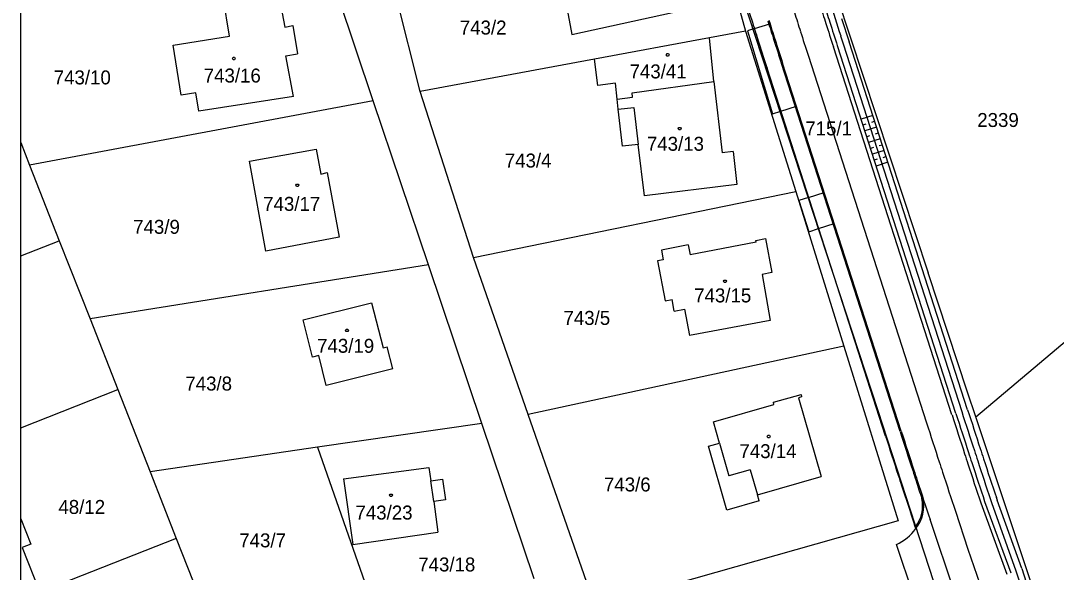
# Model space of a CAD drawing. Extents: x -639590 to -639298, y -1193269 to -1192863.
# Drawn here: x -639590.4 to -639464.3, y -1193117.1 to -1193049.8 of the extents above; entities that cross this region are included whole.
import ezdxf

# ---------------------------------------------------------------- set-up
doc = ezdxf.new("R2010")
doc.units = 0
for name, color, linetype in [('Vrstva 1', 7, 'Continuous'), ('Vrstva 19', 7, 'Continuous'), ('Vrstva 2', 7, 'Continuous'), ('Vrstva 20', 7, 'Continuous'), ('Vrstva 21', 7, 'Continuous'), ('Vrstva 4', 7, 'Continuous'), ('Vrstva 5', 7, 'Continuous'), ('Vrstva 61', 7, 'Continuous')]:
    doc.layers.add(name, color=color, linetype=linetype)

msp = doc.modelspace()

# ---------------------------------------------------------------- linework, layer by layer
at = {"layer": 'Vrstva 1'}
for p, q in [((-639507.5, -1193031.78), (-639502.09, -1193051.09)), ((-639506.87, -1193033.57), (-639486.01, -1193097.33)), ((-639547.47, -1193059.58), (-639554.02, -1193040.01)), ((-639559.45, -1193044.19), (-639558.24, -1193050.62)), ((-639541.72, -1193058.45), (-639545.4, -1193043.83)), ((-639492.18, -1193043.2), (-639479.86, -1193080.55)), ((-639564.97, -1193051.71), (-639566.02, -1193045.25)), ((-639524.07, -1193047.11), (-639523.28, -1193051.49)), ((-639523.28, -1193051.49), (-639511.02, -1193048.83)), ((-639558.24, -1193050.62), (-639557.26, -1193050.41)), ((-639557.26, -1193050.41), (-639556.66, -1193053.85)), ((-639571.83, -1193052.82), (-639564.97, -1193051.71)), ((-639506.48, -1193051.9), (-639520.51, -1193054.51)), ((-639502.09, -1193051.09), (-639506.48, -1193051.9)), ((-639505.97, -1193057.23), (-639506.48, -1193051.9)), ((-639502.09, -1193051.09), (-639495.98, -1193070.66)), ((-639570.85, -1193058.91), (-639571.83, -1193052.82)), ((-639474.06, -1193098.11), (-639420.3, -1193052.71)), ((-639558.11, -1193054.1), (-639556.66, -1193053.85)), ((-639557.17, -1193059.07), (-639558.11, -1193054.1)), ((-639520.51, -1193054.51), (-639541.72, -1193058.45)), ((-639520.08, -1193057.71), (-639520.51, -1193054.51)), ((-639517.95, -1193057.42), (-639520.08, -1193057.71)), ((-639517.76, -1193059.39), (-639517.95, -1193057.42)), ((-639515.93, -1193058.62), (-639505.97, -1193057.23)), ((-639505.97, -1193057.23), (-639504.97, -1193065.92)), ((-639569.05, -1193058.62), (-639570.85, -1193058.91)), ((-639568.69, -1193060.84), (-639569.05, -1193058.62)), ((-639557.17, -1193059.07), (-639568.69, -1193060.84)), ((-639535.24, -1193078.67), (-639541.72, -1193058.45)), ((-639517.76, -1193059.39), (-639515.86, -1193059.16)), ((-639517.61, -1193060.62), (-639517.76, -1193059.39)), ((-639515.86, -1193059.16), (-639515.93, -1193058.62)), ((-639547.47, -1193059.58), (-639589.3, -1193067.44)), ((-639540.73, -1193079.59), (-639547.47, -1193059.58)), ((-639517.08, -1193065.13), (-639517.61, -1193060.62)), ((-639590.39, -1193064.66), (-639589.3, -1193067.44)), ((-639562.54, -1193066.96), (-639554.39, -1193065.47)), ((-639554.39, -1193065.47), (-639553.85, -1193068.54)), ((-639515.18, -1193064.91), (-639517.08, -1193065.13)), ((-639514.42, -1193071.19), (-639515.18, -1193064.91)), ((-639503.63, -1193065.77), (-639504.97, -1193065.92)), ((-639503.63, -1193065.77), (-639503.17, -1193069.78)), ((-639560.52, -1193077.92), (-639562.54, -1193066.96)), ((-639589.3, -1193067.44), (-639585.69, -1193076.64)), ((-639553.85, -1193068.54), (-639553.06, -1193068.33)), ((-639553.06, -1193068.33), (-639551.62, -1193076.2)), ((-639535.24, -1193078.67), (-639495.98, -1193070.66)), ((-639503.17, -1193069.78), (-639514.42, -1193071.19)), ((-639495.98, -1193070.66), (-639490.12, -1193089.51)), ((-639590.39, -1193078.48), (-639585.69, -1193076.64)), ((-639585.69, -1193076.64), (-639581.95, -1193086.16)), ((-639551.62, -1193076.2), (-639560.52, -1193077.92)), ((-639509.09, -1193077.16), (-639512.35, -1193077.79)), ((-639509.09, -1193077.16), (-639508.86, -1193078.35)), ((-639500.81, -1193076.8), (-639508.86, -1193078.35)), ((-639500.85, -1193076.6), (-639499.66, -1193076.39)), ((-639500.81, -1193076.8), (-639500.85, -1193076.6)), ((-639499.66, -1193076.39), (-639498.92, -1193080.53)), ((-639512.35, -1193077.79), (-639512.12, -1193078.98)), ((-639540.73, -1193079.59), (-639581.95, -1193086.16)), ((-639534.22, -1193098.9), (-639540.73, -1193079.59)), ((-639528.59, -1193097.82), (-639535.24, -1193078.67)), ((-639512.12, -1193078.98), (-639512.82, -1193079.11)), ((-639512.82, -1193079.11), (-639511.88, -1193083.98)), ((-639498.92, -1193080.53), (-639500.1, -1193080.74)), ((-639500.1, -1193080.74), (-639499.09, -1193086.35)), ((-639475.06, -1193095.11), (-639479.86, -1193080.55)), ((-639555.99, -1193086.3), (-639547.67, -1193084.22)), ((-639547.67, -1193084.22), (-639546.23, -1193089.69)), ((-639511.88, -1193083.98), (-639511.05, -1193083.82)), ((-639510.78, -1193085.21), (-639511.05, -1193083.82)), ((-639510.78, -1193085.21), (-639509.54, -1193084.97)), ((-639509.54, -1193084.97), (-639508.92, -1193088.21)), ((-639581.95, -1193086.16), (-639578.57, -1193094.79)), ((-639554.86, -1193090.83), (-639555.99, -1193086.3)), ((-639499.09, -1193086.35), (-639508.92, -1193088.21)), ((-639546.23, -1193089.69), (-639545.74, -1193089.57)), ((-639545.08, -1193092.25), (-639545.74, -1193089.57)), ((-639490.12, -1193089.51), (-639528.59, -1193097.82)), ((-639490.12, -1193089.51), (-639483.53, -1193110.77)), ((-639554.09, -1193090.64), (-639554.86, -1193090.83)), ((-639553.18, -1193094.27), (-639554.09, -1193090.64)), ((-639545.08, -1193092.25), (-639553.18, -1193094.27)), ((-639590.39, -1193099.43), (-639578.57, -1193094.79)), ((-639578.57, -1193094.79), (-639574.64, -1193104.8)), ((-639498.72, -1193096.33), (-639495.35, -1193095.38)), ((-639495.27, -1193095.66), (-639495.66, -1193095.77)), ((-639495.66, -1193095.77), (-639492.91, -1193105.39)), ((-639495.35, -1193095.38), (-639495.27, -1193095.66)), ((-639474.06, -1193098.11), (-639475.06, -1193095.11)), ((-639506, -1193098.71), (-639498.64, -1193096.62)), ((-639498.64, -1193096.62), (-639498.72, -1193096.33)), ((-639486.01, -1193097.33), (-639448.4, -1193212.6)), ((-639520.42, -1193121.23), (-639528.59, -1193097.82)), ((-639466.59, -1193120.49), (-639474.06, -1193098.11)), ((-639534.22, -1193098.9), (-639554.24, -1193101.82)), ((-639527.84, -1193117.84), (-639534.22, -1193098.9)), ((-639505.26, -1193101.31), (-639506, -1193098.71)), ((-639554.24, -1193101.82), (-639574.64, -1193104.8)), ((-639554.24, -1193101.82), (-639547.48, -1193121.13)), ((-639506.61, -1193101.69), (-639505.26, -1193101.31)), ((-639504.4, -1193109.48), (-639506.61, -1193101.69)), ((-639574.64, -1193104.8), (-639571.44, -1193112.95)), ((-639551.08, -1193105.65), (-639540.67, -1193104.28)), ((-639540.67, -1193104.28), (-639540.44, -1193105.91)), ((-639551.08, -1193105.65), (-639549.93, -1193113.68)), ((-639540.44, -1193105.91), (-639539.03, -1193105.71)), ((-639539.03, -1193105.71), (-639538.67, -1193108.24)), ((-639500.65, -1193107.6), (-639492.91, -1193105.39)), ((-639538.67, -1193108.24), (-639540.09, -1193108.43)), ((-639540.09, -1193108.43), (-639539.57, -1193112.18)), ((-639500.43, -1193108.36), (-639504.4, -1193109.48)), ((-639500.43, -1193108.36), (-639500.65, -1193107.6)), ((-639590.39, -1193110.53), (-639589.17, -1193113.63)), ((-639483.53, -1193110.77), (-639520.42, -1193121.23)), ((-639549.93, -1193113.68), (-639539.57, -1193112.18)), ((-639589.17, -1193113.63), (-639590.23, -1193114.05)), ((-639571.44, -1193112.95), (-639588.08, -1193119.47)), ((-639571.44, -1193112.95), (-639566.95, -1193124.39)), ((-639590.23, -1193114.05), (-639588.08, -1193119.47))]:
    msp.add_line(p, q, dxfattribs=at)
at = {"layer": 'Vrstva 19'}
for p, q in [((-639476.96, -1193097.85), (-639491.4, -1193053.02)), ((-639483.15, -1193099.84), (-639497.59, -1193055.02)), ((-639473.46, -1193108.58), (-639470.27, -1193117.3)), ((-639476.66, -1193119.47), (-639479.62, -1193110.62))]:
    msp.add_line(p, q, dxfattribs=at)
for points in [[(-639494.49, -1193054.02), (-639480.05, -1193098.85)], [(-639476.54, -1193109.6), (-639475.01, -1193114.22), (-639473.58, -1193118.45)]]:
    msp.add_lwpolyline(points, dxfattribs=at)
for centre, radius, start, end in [((-639019.03, -1192899.3), 496.75, 197.3984, 197.6812), ((-639019.03, -1192899.3), 496.25, 197.3984, 197.6812), ((-639019.03, -1192899.3), 500, 197.3984, 197.6812), ((-639019.03, -1192899.3), 503.25, 197.3984, 197.6812), ((-638521.16, -1192740.02), 1019.48, 197.71175, 197.87981), ((-638521.16, -1192740.02), 1018.98, 197.71175, 197.87981), ((-638521.16, -1192740.02), 1022.73, 197.71175, 197.87981), ((-638521.16, -1192740.02), 1027.98, 197.71175, 197.87981), ((-638521.16, -1192740.02), 1025.98, 197.71175, 197.87981), ((-638106.92, -1192657.52), 1439.06, 197.81743, 198.01605), ((-638106.92, -1192657.52), 1445.56, 197.81743, 198.01605), ((-638106.92, -1192657.52), 1442.31, 197.81743, 198.01605), ((-638765.42, -1192871.3), 749.98, 198.04406, 198.14436), ((-638765.42, -1192871.3), 746.73, 198.04406, 198.14436), ((-638765.42, -1192871.3), 753.23, 198.04406, 198.14436), ((-638033.46, -1192630.51), 1520.53, 198.17747, 198.36593), ((-638033.46, -1192630.51), 1517.28, 198.17747, 198.36593), ((-638033.46, -1192630.51), 1523.78, 198.17747, 198.36593)]:
    msp.add_arc(centre, radius, start, end, dxfattribs=at)
at = {"layer": 'Vrstva 20'}
for p, q in [((-639501.03, -1193050.79), (-639499.13, -1193050.19)), ((-639485.05, -1193100.45), (-639499.49, -1193055.63)), ((-639483.29, -1193099.89), (-639497.73, -1193055.06)), ((-639497.81, -1193060.85), (-639495.9, -1193060.25)), ((-639494.42, -1193071.38), (-639492.51, -1193070.78)), ((-639493.2, -1193075.16), (-639491.3, -1193074.55)), ((-639480.49, -1193108.01), (-639480.64, -1193108.04)), ((-639481.37, -1193111.72), (-639481.52, -1193111.26))]:
    msp.add_line(p, q, dxfattribs=at)
for points in [[(-639501.03, -1193050.79), (-639501.87, -1193051.05), (-639498.81, -1193061.16), (-639497.81, -1193060.85)], [(-639495.62, -1193071.76), (-639494.39, -1193075.55), (-639493.2, -1193075.16), (-639494.42, -1193071.38)]]:
    msp.add_lwpolyline(points, close=True, dxfattribs=at)
for centre, radius, start, end in [((-638520.02, -1192743.51), 1028.01, 197.19976, 197.36783), ((-639019.03, -1192899.3), 505.25, 197.3984, 197.6812), ((-639019.03, -1192899.3), 503.4, 197.3984, 197.6812), ((-638521.16, -1192740.02), 1026.13, 197.71175, 197.87981), ((-638106.92, -1192657.52), 1445.71, 197.81743, 198.01605), ((-638106.92, -1192657.52), 1447.56, 197.81743, 198.01605), ((-638765.42, -1192871.3), 753.38, 198.04406, 198.14436), ((-638765.42, -1192871.3), 755.23, 198.04406, 198.14436), ((-638033.46, -1192630.51), 1523.93, 198.17747, 198.26209), ((-638033.46, -1192630.51), 1525.78, 198.17747, 198.36593), ((-639484.89, -1193108.93), 4.35, 322.9448, 11.789)]:
    msp.add_arc(centre, radius, start, end, dxfattribs=at)
at = {"layer": 'Vrstva 21'}
for p, q in [((-639490.41, -1193049.57), (-639489.49, -1193052.41)), ((-639476.49, -1193097.69), (-639490.92, -1193052.87)), ((-639475.06, -1193097.24), (-639489.49, -1193052.41)), ((-639486.61, -1193061.37), (-639488.04, -1193061.83)), ((-639486.74, -1193062.2), (-639486.38, -1193062.08)), ((-639487.45, -1193062.43), (-639487.81, -1193062.54)), ((-639486.15, -1193062.8), (-639487.58, -1193063.26)), ((-639486.99, -1193063.86), (-639487.35, -1193063.97)), ((-639485.69, -1193064.22), (-639487.12, -1193064.68)), ((-639486.28, -1193063.63), (-639485.92, -1193063.51)), ((-639486.53, -1193065.28), (-639486.89, -1193065.4)), ((-639485.23, -1193065.65), (-639486.66, -1193066.11)), ((-639485.82, -1193065.05), (-639485.46, -1193064.94)), ((-639486.07, -1193066.71), (-639486.43, -1193066.83)), ((-639484.77, -1193067.08), (-639486.2, -1193067.54)), ((-639485.36, -1193066.48), (-639485, -1193066.37)), ((-639472.98, -1193108.41), (-639469.8, -1193117.13)), ((-639471.58, -1193107.89), (-639471.44, -1193108.27)), ((-639468.47, -1193116.61), (-639471.44, -1193108.27)), ((-639481.66, -1193119.86), (-639483.73, -1193113.68)), ((-639468.47, -1193116.61), (-639464.73, -1193127.9))]:
    msp.add_line(p, q, dxfattribs=at)
for points in [[(-639490.52, -1193051.69), (-639490.21, -1193052.64), (-639475.77, -1193097.47)], [(-639472.28, -1193108.17), (-639472.14, -1193108.53), (-639469.18, -1193116.87), (-639465.39, -1193128.31)]]:
    msp.add_lwpolyline(points, dxfattribs=at)
for centre, radius, start, end in [((-639019.03, -1192899.3), 495.5, 197.3984, 197.9106), ((-638106.92, -1192657.52), 1437.06, 197.81743, 198.01605), ((-638106.92, -1192657.52), 1438.56, 197.81743, 198.01605), ((-638106.75, -1192657.47), 1437.99, 197.81738, 198.01594), ((-638765.42, -1192871.3), 746.23, 198.04406, 198.14436), ((-638765.42, -1192871.3), 745.48, 198.04406, 198.14426), ((-638765.42, -1192871.3), 744.73, 198.04406, 198.14436), ((-638033.46, -1192630.51), 1516.78, 198.17747, 198.36593), ((-638033.46, -1192630.51), 1516.78, 198.17747, 198.36565), ((-638033.46, -1192630.51), 1516.03, 198.17752, 198.36523), ((-638033.46, -1192630.51), 1515.28, 198.17747, 198.36593), ((-639484.89, -1193108.93), 4.5, 321.646, 11.789), ((-639486.13, -1193108.36), 5.83, 294.2641, 324.7722)]:
    msp.add_arc(centre, radius, start, end, dxfattribs=at)
at = {"layer": 'Vrstva 4'}
for p, q in [((-639517.61, -1193060.62), (-639515.71, -1193060.39)), ((-639515.71, -1193060.39), (-639515.18, -1193064.91)), ((-639505.26, -1193101.31), (-639504.12, -1193105.3)), ((-639501.53, -1193104.56), (-639504.12, -1193105.3)), ((-639501.53, -1193104.56), (-639500.65, -1193107.6)), ((-639540.09, -1193108.43), (-639540.44, -1193105.91))]:
    msp.add_line(p, q, dxfattribs=at)
at = {"layer": 'Vrstva 5'}
for points in [[(-639564.34, -1193054.28), (-639564.25, -1193054.43), (-639564.34, -1193054.58), (-639564.52, -1193054.58), (-639564.61, -1193054.43), (-639564.52, -1193054.28)], [(-639511.49, -1193053.83), (-639511.4, -1193053.98), (-639511.49, -1193054.13), (-639511.67, -1193054.13), (-639511.76, -1193053.98), (-639511.67, -1193053.83)], [(-639510.03, -1193062.83), (-639509.94, -1193062.98), (-639510.03, -1193063.13), (-639510.21, -1193063.13), (-639510.3, -1193062.98), (-639510.21, -1193062.83)], [(-639556.61, -1193069.74), (-639556.52, -1193069.89), (-639556.61, -1193070.04), (-639556.79, -1193070.04), (-639556.88, -1193069.89), (-639556.79, -1193069.74)], [(-639504.52, -1193081.44), (-639504.43, -1193081.59), (-639504.52, -1193081.74), (-639504.7, -1193081.74), (-639504.79, -1193081.59), (-639504.7, -1193081.44)], [(-639550.56, -1193087.42), (-639550.47, -1193087.57), (-639550.56, -1193087.72), (-639550.74, -1193087.72), (-639550.83, -1193087.57), (-639550.74, -1193087.42)], [(-639499.19, -1193100.36), (-639499.1, -1193100.51), (-639499.19, -1193100.66), (-639499.37, -1193100.66), (-639499.46, -1193100.51), (-639499.37, -1193100.36)], [(-639545.2, -1193107.52), (-639545.11, -1193107.67), (-639545.2, -1193107.82), (-639545.38, -1193107.82), (-639545.47, -1193107.67), (-639545.38, -1193107.52)]]:
    msp.add_lwpolyline(points, close=True, dxfattribs=at)
at = {"layer": 'Vrstva 61'}
msp.add_lwpolyline([(-639590.39, -1193268.77), (-639590.39, -1192863.27)], dxfattribs=at)

# ---------------------------------------------------------------- texts
at = {"layer": 'Vrstva 2'}
for s, p in [('743/2', (-639536.91, -1193051.51)), ('743/16', (-639568.1, -1193057.36)), ('743/41', (-639516.23, -1193056.86)), ('743/10', (-639586.37, -1193057.59)), ('715/1', (-639494.83, -1193063.8)), ('2339', (-639473.88, -1193062.78)), ('743/13', (-639514.12, -1193065.68)), ('743/4', (-639531.43, -1193067.72)), ('743/17', (-639560.86, -1193073)), ('743/9', (-639576.69, -1193075.8)), ('743/15', (-639508.36, -1193084.16)), ('743/5', (-639524.28, -1193086.9)), ('743/19', (-639554.29, -1193090.3)), ('743/8', (-639570.34, -1193094.9)), ('743/14', (-639502.85, -1193103.14)), ('743/6', (-639519.35, -1193107.2)), ('48/12', (-639585.8, -1193109.94)), ('743/23', (-639549.62, -1193110.62)), ('743/7', (-639563.77, -1193114.01)), ('743/18', (-639541.97, -1193116.95))]:
    msp.add_text(s, height=1.7, dxfattribs=at).set_placement(p)

doc.saveas('drawing.dxf')
